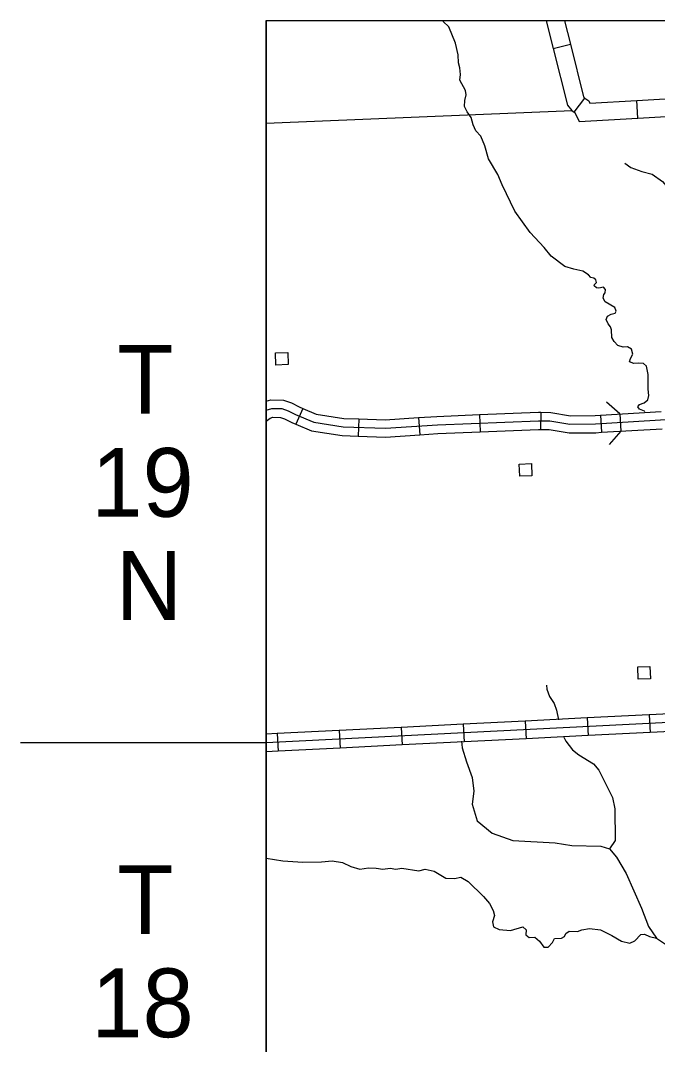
# Model space of a CAD drawing. Extents: x -0.3 to 2.65, y 0 to 1.9.
# Drawn here: x 0.3598 to 0.4246, y 0.4374 to 0.5417 of the extents above; entities that cross this region are included whole.
import ezdxf

# ---------------------------------------------------------------- set-up
doc = ezdxf.new("R2010")
doc.units = 0
for name, color, linetype in [('DSN_DRFT_DNC', 7, 'Continuous'), ('Level 14', 7, 'Continuous'), ('Level 15', 7, 'Continuous'), ('Level 19', 7, 'Continuous'), ('Level 20', 7, 'Continuous'), ('Level 29', 7, 'Continuous'), ('Level 6', 7, 'Continuous'), ('SHET_Annotations', 7, 'Continuous')]:
    doc.layers.add(name, color=color, linetype=linetype)

msp = doc.modelspace()

# ---------------------------------------------------------------- linework, layer by layer
at = {"layer": 'DSN_DRFT_DNC'}
msp.add_lwpolyline([(0.38477, 0.54167), (1.0319, 0.54167), (1.0319, 0.1443), (0.38477, 0.1443)], close=True, dxfattribs=at)
at = {"layer": 'Level 14'}
for points in [[(0.40499, 0.53351), (0.40512, 0.53408), (0.40508, 0.53455), (0.40448, 0.53558), (0.40455, 0.53616), (0.40449, 0.53685), (0.40434, 0.53737), (0.40432, 0.53816), (0.40404, 0.53936), (0.40336, 0.54101), (0.40278, 0.54157), (0.40277, 0.54164)], [(0.42331, 0.50184), (0.42327, 0.50188), (0.42279, 0.5021), (0.42262, 0.50231), (0.42279, 0.50256), (0.42325, 0.50272), (0.42362, 0.50304), (0.42374, 0.50348), (0.42365, 0.50411), (0.42366, 0.50561), (0.4235, 0.50645), (0.42319, 0.50672), (0.42267, 0.50678), (0.42219, 0.50672), (0.42176, 0.50692), (0.42186, 0.50724), (0.42209, 0.50769), (0.42197, 0.50821), (0.42156, 0.50843), (0.42112, 0.5084), (0.42058, 0.50857), (0.42019, 0.50897), (0.41997, 0.5094), (0.41992, 0.51018), (0.41983, 0.51048), (0.41959, 0.51078), (0.41937, 0.51122), (0.41951, 0.51157), (0.41989, 0.51175), (0.42029, 0.51185), (0.42039, 0.51206), (0.42026, 0.51243), (0.41929, 0.51303), (0.41907, 0.51338), (0.41915, 0.51376), (0.41929, 0.51394), (0.41932, 0.51426), (0.41911, 0.5145), (0.41862, 0.51441), (0.41841, 0.51444), (0.41815, 0.51466), (0.41818, 0.51479), (0.41839, 0.51498), (0.41834, 0.51527), (0.41812, 0.51541), (0.41782, 0.5155), (0.41758, 0.51577), (0.417, 0.51613), (0.41608, 0.51634), (0.41516, 0.51663), (0.41377, 0.51768), (0.41306, 0.51856), (0.41165, 0.52007), (0.41009, 0.52226), (0.4088, 0.52494), (0.40837, 0.52598), (0.4074, 0.52758), (0.40703, 0.52891), (0.40662, 0.52988), (0.40611, 0.53044), (0.40583, 0.53104), (0.40564, 0.53178), (0.40524, 0.53237), (0.40497, 0.53292), (0.40499, 0.53351)], [(0.42127, 0.52715), (0.4219, 0.52671), (0.423, 0.5263), (0.42408, 0.52603), (0.42511, 0.52528), (0.42601, 0.52421), (0.42703, 0.52356), (0.42796, 0.5232), (0.42919, 0.52232), (0.43038, 0.52116), (0.43162, 0.52023), (0.43294, 0.51969), (0.43434, 0.51961), (0.436, 0.51987)], [(0.41332, 0.47397), (0.41334, 0.47356), (0.4136, 0.47283), (0.41408, 0.4721), (0.41434, 0.47145), (0.41454, 0.47044)], [(0.40465, 0.46828), (0.40473, 0.46761), (0.40515, 0.46617), (0.40573, 0.46457), (0.4059, 0.46319), (0.40573, 0.46186), (0.40625, 0.46018), (0.40779, 0.45892), (0.40988, 0.45815), (0.41418, 0.45793), (0.41589, 0.45767), (0.41883, 0.45759), (0.41971, 0.45731), (0.42043, 0.45647), (0.42141, 0.4548), (0.42298, 0.45128), (0.42368, 0.4494), (0.42451, 0.44823)], [(0.41509, 0.46868), (0.41528, 0.46828), (0.41594, 0.4674), (0.41659, 0.46687), (0.41811, 0.46596), (0.41862, 0.46532), (0.42003, 0.46253), (0.42028, 0.46139), (0.42029, 0.45815), (0.41971, 0.45731)], [(0.38476, 0.45635), (0.38646, 0.4561), (0.38851, 0.45596), (0.39041, 0.456), (0.3915, 0.4561), (0.39254, 0.45591), (0.3934, 0.45551), (0.3943, 0.45525), (0.3952, 0.45537), (0.39598, 0.45536), (0.39666, 0.45523), (0.39741, 0.45535), (0.39798, 0.45524), (0.39859, 0.45536), (0.40031, 0.45508), (0.40097, 0.45525), (0.40187, 0.45503), (0.40305, 0.45433), (0.40395, 0.45429), (0.40459, 0.45442), (0.40535, 0.454), (0.40691, 0.45245), (0.4075, 0.45174), (0.40788, 0.45104), (0.40801, 0.45051), (0.40782, 0.44987), (0.40793, 0.44937), (0.4085, 0.44911), (0.40964, 0.44901), (0.41089, 0.44938), (0.41124, 0.44908), (0.41121, 0.44855), (0.41156, 0.44827), (0.41211, 0.44831), (0.41261, 0.44792), (0.41303, 0.44731), (0.41349, 0.4473), (0.41392, 0.44777), (0.41413, 0.44817), (0.41485, 0.44822), (0.41515, 0.44837), (0.41529, 0.4487), (0.41562, 0.44893), (0.41646, 0.44889), (0.41689, 0.44908), (0.41768, 0.44921), (0.4188, 0.44905), (0.41997, 0.44848), (0.42095, 0.44792), (0.4218, 0.44772), (0.42229, 0.44795), (0.42291, 0.4486), (0.4233, 0.44863), (0.42379, 0.4484), (0.42451, 0.44823)], [(0.42451, 0.44823), (0.42695, 0.4466), (0.42803, 0.44602), (0.42876, 0.44539), (0.42951, 0.44493), (0.43048, 0.44508), (0.43145, 0.44543), (0.43276, 0.44539), (0.43387, 0.44515), (0.43548, 0.44539), (0.43714, 0.44415), (0.43839, 0.44368), (0.43843, 0.44365)]]:
    msp.add_lwpolyline(points, dxfattribs=at)
at = {"layer": 'Level 15'}
for p, q in [((0.41329, 0.54164), (0.414, 0.53881)), ((0.41514, 0.54164), (0.41574, 0.53925)), ((0.414, 0.53881), (0.41574, 0.53925)), ((0.41614, 0.53233), (0.41721, 0.53377)), ((0.42262, 0.53172), (0.42252, 0.53352)), ((0.38849, 0.50217), (0.3878, 0.50055)), ((0.41272, 0.50177), (0.41269, 0.50001)), ((0.42077, 0.5016), (0.42088, 0.49985)), ((0.3942, 0.50109), (0.39415, 0.49934)), ((0.40029, 0.50123), (0.40041, 0.49948)), ((0.40649, 0.50153), (0.40656, 0.49977)), ((0.41881, 0.50148), (0.41892, 0.49973)), ((0.41114, 0.47032), (0.41123, 0.46853)), ((0.41745, 0.47064), (0.41754, 0.46884)), ((0.42376, 0.47095), (0.42385, 0.46916)), ((0.39221, 0.46937), (0.3923, 0.46757)), ((0.39852, 0.46968), (0.39861, 0.46789)), ((0.40483, 0.47), (0.40492, 0.46821)), ((0.3859, 0.46905), (0.38476, 0.46899)), ((0.3859, 0.46905), (0.38599, 0.46726)), ((0.38599, 0.46726), (0.38476, 0.46719))]:
    msp.add_line(p, q, dxfattribs=at)
for points in [[(0.41574, 0.53925), (0.41709, 0.53388), (0.41714, 0.53383), (0.41721, 0.53377)], [(0.414, 0.53881), (0.41545, 0.53304), (0.4159, 0.53251), (0.41614, 0.53233)], [(0.41721, 0.53377), (0.41762, 0.53347), (0.41773, 0.53324), (0.42252, 0.53352)], [(0.42252, 0.53352), (0.42882, 0.53388)], [(0.41614, 0.53233), (0.41619, 0.53229), (0.41664, 0.53138), (0.42262, 0.53172)], [(0.42262, 0.53172), (0.42893, 0.53209)], [(0.38476, 0.50198), (0.38477, 0.50199), (0.38534, 0.50216), (0.38638, 0.50214), (0.387, 0.50193), (0.38777, 0.50154), (0.38962, 0.50075), (0.3926, 0.50028), (0.39691, 0.50015), (0.40221, 0.50049), (0.4125, 0.50091), (0.41366, 0.50089), (0.41569, 0.50055), (0.41831, 0.50059), (0.42878, 0.50123), (0.43404, 0.50182), (0.43761, 0.50209), (0.45588, 0.50304)], [(0.38476, 0.50289), (0.38523, 0.50302), (0.38653, 0.50299), (0.38734, 0.50273), (0.38814, 0.50232), (0.38849, 0.50217)], [(0.38849, 0.50217), (0.38986, 0.50158), (0.39268, 0.50114), (0.3942, 0.50109)], [(0.40649, 0.50153), (0.41249, 0.50177), (0.41272, 0.50177)], [(0.41272, 0.50177), (0.41374, 0.50175), (0.41575, 0.50142), (0.41828, 0.50145), (0.41881, 0.50148)], [(0.41881, 0.50148), (0.42498, 0.50186)], [(0.38476, 0.50088), (0.38517, 0.50118), (0.38546, 0.50126), (0.38623, 0.50124), (0.38665, 0.5011), (0.38739, 0.50073), (0.3878, 0.50055)], [(0.3878, 0.50055), (0.38937, 0.49988), (0.39252, 0.49939), (0.39415, 0.49934)], [(0.3942, 0.50109), (0.39689, 0.50101), (0.40029, 0.50123)], [(0.40029, 0.50123), (0.40216, 0.50135), (0.40649, 0.50153)], [(0.40041, 0.49948), (0.40226, 0.4996), (0.40656, 0.49977)], [(0.40656, 0.49977), (0.41251, 0.50001), (0.41269, 0.50001)], [(0.41269, 0.50001), (0.41358, 0.5), (0.41562, 0.49966), (0.41834, 0.49969), (0.41892, 0.49973)], [(0.41892, 0.49973), (0.42509, 0.5001)], [(0.39415, 0.49934), (0.39692, 0.49925), (0.40041, 0.49948)], [(0.48692, 0.47286), (0.46544, 0.47185), (0.43853, 0.47082), (0.38476, 0.46811)], [(0.41114, 0.47032), (0.40483, 0.47)], [(0.41745, 0.47064), (0.41114, 0.47032)], [(0.42376, 0.47095), (0.41745, 0.47064)], [(0.43007, 0.47127), (0.42376, 0.47095)], [(0.39221, 0.46937), (0.3859, 0.46905)], [(0.39852, 0.46968), (0.39221, 0.46937)], [(0.40483, 0.47), (0.39852, 0.46968)], [(0.43016, 0.46948), (0.42385, 0.46916)], [(0.41123, 0.46853), (0.40492, 0.46821)], [(0.41754, 0.46884), (0.41123, 0.46853)], [(0.42385, 0.46916), (0.41754, 0.46884)], [(0.3923, 0.46757), (0.38599, 0.46726)], [(0.39861, 0.46789), (0.3923, 0.46757)], [(0.40492, 0.46821), (0.39861, 0.46789)]]:
    msp.add_lwpolyline(points, dxfattribs=at)
at = {"layer": 'Level 19'}
for points in [[(0.38576, 0.50658), (0.38571, 0.50782), (0.38696, 0.50787), (0.38701, 0.50662)], [(0.41059, 0.49526), (0.41054, 0.4965), (0.41179, 0.49655), (0.41183, 0.4953)], [(0.42263, 0.4746), (0.42259, 0.47584), (0.42383, 0.47589), (0.42388, 0.47464)]]:
    msp.add_lwpolyline(points, close=True, dxfattribs=at)
at = {"layer": 'Level 20'}
msp.add_line((0.41592, 0.53248), (0.38476, 0.53116), dxfattribs=at)
at = {"layer": 'Level 29'}
for points in [[(0.41943, 0.50283), (0.42077, 0.50164)], [(0.42088, 0.49985), (0.41969, 0.4985)]]:
    msp.add_lwpolyline(points, dxfattribs=at)
at = {"layer": 'Level 6'}
msp.add_line((0.38476, 0.54164), (0.38476, 0.14427), dxfattribs=at)
msp.add_lwpolyline([(1.03189, 0.54164), (1.03189, 0.54164), (0.38476, 0.54164)], dxfattribs=at)
at = {"layer": 'SHET_Annotations'}
msp.add_line((0.35976, 0.46813), (0.38476, 0.46813), dxfattribs=at)

# ---------------------------------------------------------------- texts
for s, p in [('T', (0.36962, 0.50163)), ('19', (0.36698, 0.49113)), ('N', (0.36946, 0.48063)), ('T', (0.36962, 0.44863)), ('18', (0.36698, 0.43813))]:
    msp.add_text(s, height=0.007, dxfattribs=at).set_placement(p)

doc.saveas('drawing.dxf')
